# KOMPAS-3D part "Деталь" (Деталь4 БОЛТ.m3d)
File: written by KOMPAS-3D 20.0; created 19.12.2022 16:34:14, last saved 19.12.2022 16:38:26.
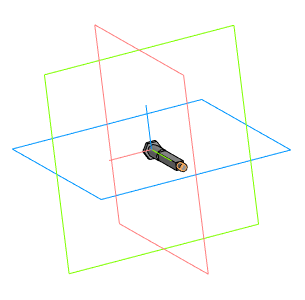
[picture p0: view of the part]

Document properties: Полное имя файла: C:\Users\Семья\Desktop\ДЕТАЛИ ДЛЯ СБОРЩИКА БОРЩЕВИКА\ДЕТАЛИ ДЛЯ ФИНАЛА\Деталь4 БОЛТ.m3d

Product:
- Part/product: Деталь
    Масса: 0.000750111
  - Body: Тело 1
      Масса: 0.000781535

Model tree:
1. Эскиз:1
2. Элемент выдавливания:1
     Расстояние 1 = 1
3. Эскиз:2  (with: Элемент выдавливания:1)
4. Элемент выдавливания:2
     Расстояние 1 = 5
5. Эскиз:3  (with: Элемент выдавливания:2)
6. Элемент выдавливания:5
     Расстояние 1 = 10
7. Эскиз:5  (with: Элемент выдавливания:5)
8. Элемент выдавливания:6
     Расстояние 1 = 2
9. Условное изображение резьбы:2  (with: Элемент выдавливания:6)  (labels: M2; cil0_24705-2004 coarse)
     Длина резьбы = 2; Шаг резьбы = 0.4; Номинальный диаметр резьбы = 2
10. Подгонка:2  (with: Элемент выдавливания:6)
